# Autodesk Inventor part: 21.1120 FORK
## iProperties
Created: 2007-04
Part Number: 21.1120 FORK
Document SubType Name: Modeling
Designer: Andy Moles
Material: Steel
Mass: 247.51 g
Surface Area: 192.735 cm^2
Volume: 31.53 cm^3
Density: 7.85 g/cm^3
Author: Andy Moles
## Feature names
1. Base1
